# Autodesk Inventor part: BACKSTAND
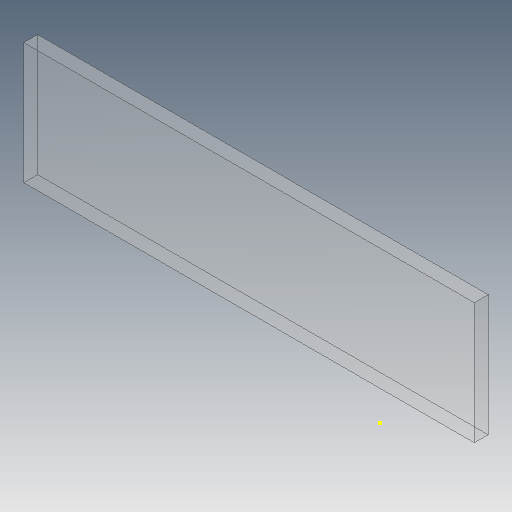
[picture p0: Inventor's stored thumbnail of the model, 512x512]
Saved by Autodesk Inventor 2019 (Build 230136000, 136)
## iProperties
Created: 2019-10
Part Number: BACKSTAND
Material: PET Plastic
Document SubType Name: Modeling
Designer: hp
Density: 1.541 g/cm^3
Appearance: Polycarbonate - Clear
Author: hp
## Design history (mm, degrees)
sketch "Sketch1"
  geometry: L1 (318.219, 8.966)-(318.219, -6.034); L2 (-102.849, 43.663)-(27.151, 43.663); L3 (27.151, 43.663)-(27.151, 8.663); L4 (27.151, 8.663)-(-102.849, 8.663); L5 (-102.849, 8.663)-(-102.849, 43.663); 1 further point
  constraints: 10 end point, 2 parallel, 1 horizontal, 1 perpendicular
  dimensions: "d6" = 130 distance of L3.end L4.end; "d7" = 35 distance of L2.end L3.end
extrude "Extrusion1" new body sketch "Sketch1" distance "d2" = 4; taper "d3" = 0 deg
sketch "Sketch2"
  geometry: 1 further point
body "Solid1"
